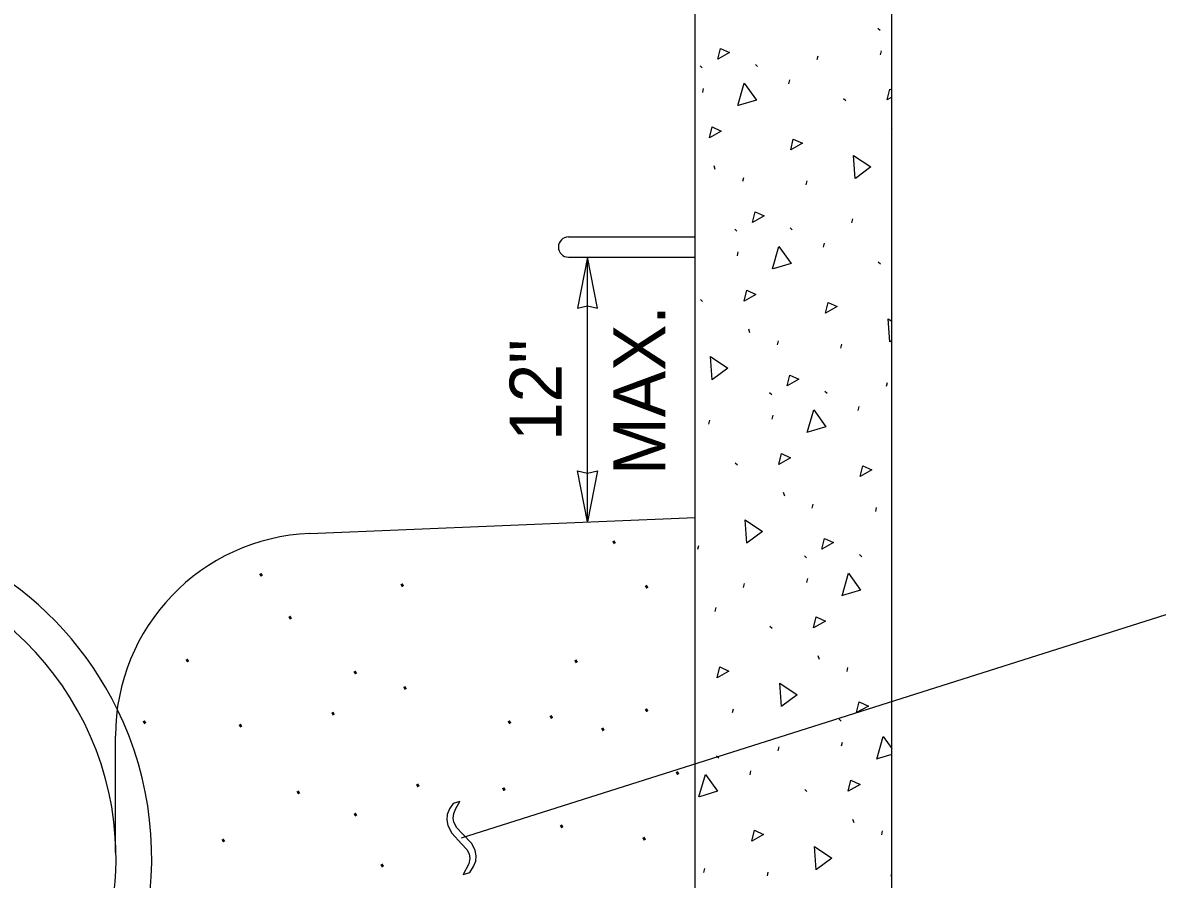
# Model space of a CAD drawing. Extents: x 99862 to 103151, y 100000 to 102076.
# Drawn here: x 101001.8 to 101351.4, y 100759.3 to 101023.2 of the extents above; entities that cross this region are included whole.
import ezdxf

# ---------------------------------------------------------------- set-up
doc = ezdxf.new("R2010")
doc.units = 0
for name, color, linetype in [('Level 1', 7, 'Continuous'), ('Level 15', 7, 'Continuous'), ('Level 16', 7, 'Continuous'), ('Level 17', 7, 'Continuous'), ('Level 18', 7, 'Continuous'), ('Level 20', 7, 'Continuous')]:
    doc.layers.add(name, color=color, linetype=linetype)

msp = doc.modelspace()

# ---------------------------------------------------------------- linework, layer by layer
at = {"layer": 'Level 1'}
msp.add_arc((100936.81, 100765.78), 104.72, 154.3283, 26.0354, dxfattribs=at)
at = {"layer": 'Level 15'}
for p, q in [((101175.82, 100869.45), (101175.82, 100951.01)), ((101136.97, 100772.06), (101356.07, 100841.49))]:
    msp.add_line(p, q, dxfattribs=at)
for points in [[(101175.82, 100951.01), (101172.73, 100935.29), (101175.82, 100936.01), (101178.9, 100935.29)], [(101175.82, 100869.45), (101172.73, 100885.17), (101175.82, 100884.45), (101178.9, 100885.17)]]:
    msp.add_lwpolyline(points, close=True, dxfattribs=at)
at = {"layer": 'Level 16'}
for p, q in [((101265.32, 101021.6), (101265.96, 101020.97)), ((101246.59, 101011.89), (101246.85, 101013.09)), ((101266.1, 101013.39), (101266.36, 101014.59)), ((101210.55, 101009.95), (101211.19, 101009.33)), ((101227.58, 101010.34), (101228.22, 101009.72)), ((101237.88, 101004.46), (101238.13, 101005.66)), ((101211.33, 101001.75), (101211.58, 101002.94)), ((101254.73, 100999.91), (101255.37, 100999.29)), ((101269.5, 100990.86), (101269.59, 100990.6)), ((101214.73, 100979.22), (101215.08, 100978.15)), ((101223.68, 100974.38), (101223.94, 100975.57)), ((101243.23, 100973.32), (101243.48, 100974.52)), ((101257.29, 100961.57), (101257.54, 100962.77)), ((101221.24, 100959.63), (101221.88, 100959)), ((101238.28, 100960.01), (101238.92, 100959.39)), ((101248.57, 100954.14), (101248.83, 100955.34)), ((101222.02, 100951.42), (101222.28, 100952.62)), ((101265.43, 100949.59), (101266.07, 100948.96)), ((101210.65, 100937.94), (101211.29, 100937.32)), ((101225.43, 100928.89), (101225.78, 100927.82)), ((101234.38, 100924.05), (101234.63, 100925.25)), ((101253.92, 100922.99), (101254.18, 100924.19)), ((101267.99, 100911.24), (101268.24, 100912.44)), ((101231.94, 100909.3), (101232.58, 100908.67)), ((101248.98, 100909.69), (101249.62, 100909.06)), ((101259.27, 100903.81), (101259.52, 100905.01)), ((101213.21, 100899.6), (101213.47, 100900.8)), ((101232.72, 100901.09), (101232.98, 100902.29)), ((101221.35, 100887.62), (101221.99, 100886.99)), ((101236.12, 100878.56), (101236.48, 100877.5)), ((101245.08, 100873.72), (101245.33, 100874.92)), ((101264.62, 100872.66), (101264.88, 100873.86)), ((101209.84, 100861.02), (101210.1, 100862.22)), ((101242.64, 100858.97), (101243.28, 100858.35)), ((101259.68, 100859.36), (101260.31, 100858.73)), ((101243.42, 100850.76), (101243.68, 100851.96)), ((101223.91, 100849.27), (101224.16, 100850.47)), ((101215.19, 100841.84), (101215.45, 100843.04)), ((101232.05, 100837.29), (101232.69, 100836.66)), ((101246.82, 100828.24), (101247.17, 100827.17)), ((101255.78, 100823.39), (101256.03, 100824.59)), ((101220.54, 100810.69), (101220.8, 100811.89)), ((101253.34, 100808.64), (101253.98, 100808.02)), ((101234.6, 100798.94), (101234.86, 100800.14)), ((101254.12, 100800.43), (101254.37, 100801.63)), ((101215.6, 100797.39), (101216.24, 100796.76)), ((101225.89, 100791.51), (101226.14, 100792.71)), ((101242.75, 100786.96), (101243.39, 100786.34)), ((101257.52, 100777.91), (101257.87, 100776.84)), ((101266.47, 100773.07), (101266.73, 100774.26)), ((101211.7, 100761.42), (101211.95, 100762.62)), ((101231.24, 100760.37), (101231.5, 100761.57))]:
    msp.add_line(p, q, dxfattribs=at)
for points in [[(101215.94, 101011.99), (101216.75, 101015.34), (101219.58, 101014.03), (101215.94, 101011.99)], [(101222.16, 100997.7), (101224.12, 101004.59), (101227.89, 100999.42), (101222.28, 100997.72)], [(101268.17, 100999.47), (101268.98, 101002.82), (101269.59, 101002.53)], [(101269.59, 101000.26), (101268.17, 100999.47)], [(101213.4, 100987.82), (101214.21, 100991.17), (101217.03, 100989.87), (101213.4, 100987.82)], [(101238.43, 100984.06), (101239.24, 100987.41), (101242.06, 100986.1), (101238.43, 100984.06)], [(101258.29, 100975.21), (101257.78, 100982.36), (101263.09, 100978.79), (101258.4, 100975.27)], [(101226.64, 100961.66), (101227.45, 100965.01), (101230.27, 100963.71), (101226.64, 100961.66)], [(101232.85, 100947.37), (101234.82, 100954.26), (101238.59, 100949.09), (101232.98, 100947.39)], [(101224.1, 100937.5), (101224.91, 100940.85), (101227.73, 100939.54), (101224.1, 100937.5)], [(101249.13, 100933.73), (101249.94, 100937.08), (101252.76, 100935.77), (101249.13, 100933.73)], [(101268.98, 100924.88), (101268.47, 100932.04), (101269.59, 100931.28)], [(101269.59, 100925.32), (101269.09, 100924.95)], [(101214.21, 100913.24), (101213.7, 100920.39), (101219.01, 100916.82), (101214.32, 100913.3)], [(101237.34, 100911.33), (101238.15, 100914.68), (101240.97, 100913.38), (101237.34, 100911.33)], [(101243.55, 100897.04), (101245.52, 100903.94), (101249.29, 100898.77), (101243.67, 100897.07)], [(101234.79, 100887.17), (101235.6, 100890.52), (101238.42, 100889.21), (101234.79, 100887.17)], [(101259.82, 100883.4), (101260.64, 100886.75), (101263.45, 100885.45), (101259.82, 100883.4)], [(101224.9, 100862.91), (101224.39, 100870.06), (101229.71, 100866.49), (101225.01, 100862.97)], [(101248.03, 100861.01), (101248.85, 100864.36), (101251.67, 100863.05), (101248.03, 100861.01)], [(101254.25, 100846.71), (101256.21, 100853.61), (101259.98, 100848.44), (101254.37, 100846.74)], [(101245.49, 100836.84), (101246.3, 100840.19), (101249.12, 100838.88), (101245.49, 100836.84)], [(101215.74, 100821.43), (101216.56, 100824.78), (101219.37, 100823.47), (101215.74, 100821.43)], [(101235.6, 100812.58), (101235.09, 100819.74), (101240.4, 100816.16), (101235.71, 100812.65)], [(101258.73, 100810.68), (101259.54, 100814.03), (101262.37, 100812.72), (101258.73, 100810.68)], [(101264.95, 100796.39), (101266.91, 100803.28), (101269.59, 100799.61)], [(101269.59, 100797.78), (101265.07, 100796.41)], [(101210.17, 100784.74), (101212.14, 100791.64), (101215.91, 100786.47), (101210.29, 100784.77)], [(101256.19, 100786.51), (101257, 100789.86), (101259.82, 100788.56), (101256.19, 100786.51)], [(101226.44, 100771.1), (101227.26, 100774.45), (101230.07, 100773.15), (101226.44, 100771.1)], [(101246.3, 100762.25), (101245.79, 100769.41), (101251.1, 100765.84), (101246.41, 100762.32)], [(101269.43, 100760.35), (101269.59, 100761.02)], [(101269.59, 100760.44), (101269.43, 100760.35)]]:
    msp.add_lwpolyline(points, dxfattribs=at)
at = {"layer": 'Level 17'}
for p, q in [((101269.59, 100583.14), (101269.59, 101611.69)), ((101209.03, 100643.69), (101209.03, 101551.14)), ((101090.22, 100865.89), (101209.03, 100870.84)), ((101030.35, 100767.6), (101030.35, 100803.46))]:
    msp.add_line(p, q, dxfattribs=at)
for centre, radius, start, end in [((100936.81, 100765.78), 104.72, 26.0354, 154.3283), ((101092.83, 100803.46), 62.48, 92.3879, 180), ((100936.81, 100765.78), 93.72, 1.118, 178.2436), ((100936.81, 100765.78), 93.72, 178.2436, 3.5092)]:
    msp.add_arc(centre, radius, start, end, dxfattribs=at)
at = {"layer": 'Level 18'}
for p, q in [((101169.97, 100957.26), (101209.03, 100957.26)), ((101169.97, 100951.01), (101209.03, 100951.01))]:
    msp.add_line(p, q, dxfattribs=at)
msp.add_arc((101169.97, 100954.14), 3.12, 90, 270, dxfattribs=at)
at = {"layer": 'Level 20'}
for p, q in [((101134.42, 100782.64), (101133.28, 100781.01)), ((101136.44, 100783.28), (101134.42, 100782.64)), ((101135.22, 100781.18), (101136.44, 100783.28)), ((101132.62, 100779.35), (101132.44, 100777.65)), ((101133.28, 100781.01), (101132.62, 100779.35)), ((101134.44, 100778.22), (101134.59, 100779.57)), ((101134.59, 100779.57), (101135.22, 100781.18)), ((101132.44, 100777.65), (101132.76, 100775.92)), ((101132.76, 100775.92), (101134.02, 100773.51)), ((101134.66, 100776.9), (101134.44, 100778.22)), ((101135.57, 100775.21), (101134.66, 100776.9)), ((101137.3, 100773.33), (101135.57, 100775.21)), ((101134.02, 100773.51), (101137.01, 100770.27)), ((101140.13, 100770.38), (101137.3, 100773.33)), ((101137.01, 100770.27), (101138.66, 100768.49)), ((101138.66, 100768.49), (101139.33, 100767.15)), ((101141.23, 100768.17), (101140.13, 100770.38)), ((101141.53, 100766.54), (101141.23, 100768.17)), ((101139.51, 100765.74), (101139.22, 100764.12)), ((101139.33, 100767.15), (101139.51, 100765.74)), ((101140.71, 100763.27), (101141.36, 100764.93)), ((101141.36, 100764.93), (101141.53, 100766.54)), ((101139.22, 100764.12), (101137.54, 100760.83)), ((101137.54, 100760.83), (101139.55, 100761.47)), ((101139.55, 100761.46), (101140.71, 100763.27))]:
    msp.add_line(p, q, dxfattribs=at)

# ---------------------------------------------------------------- texts
at = {"layer": 'Level 1'}
for p in [(101183.25, 100862.16), (101074.47, 100852.12), (101117.97, 100848.92), (101193.28, 100848.43), (101083.44, 100838.92), (101051.76, 100825.72), (101171.54, 100825.48), (101103.51, 100822.02), (101118.83, 100817.27), (101096.65, 100809.35), (101163.91, 100808.32), (101193.28, 100810.41), (101038.55, 100806.71), (101068.13, 100805.65), (101151.03, 100806.71), (101179.8, 100804.51), (101202.79, 100791.04), (101122.77, 100787.25), (101085.96, 100785.08), (101149.29, 100786.08), (101103.55, 100778.24), (101167.09, 100774.64), (101062.85, 100770.28), (101192.51, 100770.82), (101111.8, 100762.56)]:
    msp.add_text('.', height=6.3, rotation=30.9638, dxfattribs=at).set_placement(p)
at = {"layer": 'Level 20'}
for s, p in [('MAX.', (101199.82, 100883.88)), ('12"', (101167.82, 100894.36))]:
    msp.add_text(s, height=16, rotation=90, dxfattribs=at).set_placement(p)

doc.saveas('drawing.dxf')
